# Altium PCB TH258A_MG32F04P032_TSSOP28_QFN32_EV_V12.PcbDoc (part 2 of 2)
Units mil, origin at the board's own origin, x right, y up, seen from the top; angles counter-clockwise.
Board outline 4094.49 x 2637.8 mil, 2 copper layers (Top Layer, Bottom Layer); 115 components, 96 nets, 518 pads, 260 vias.
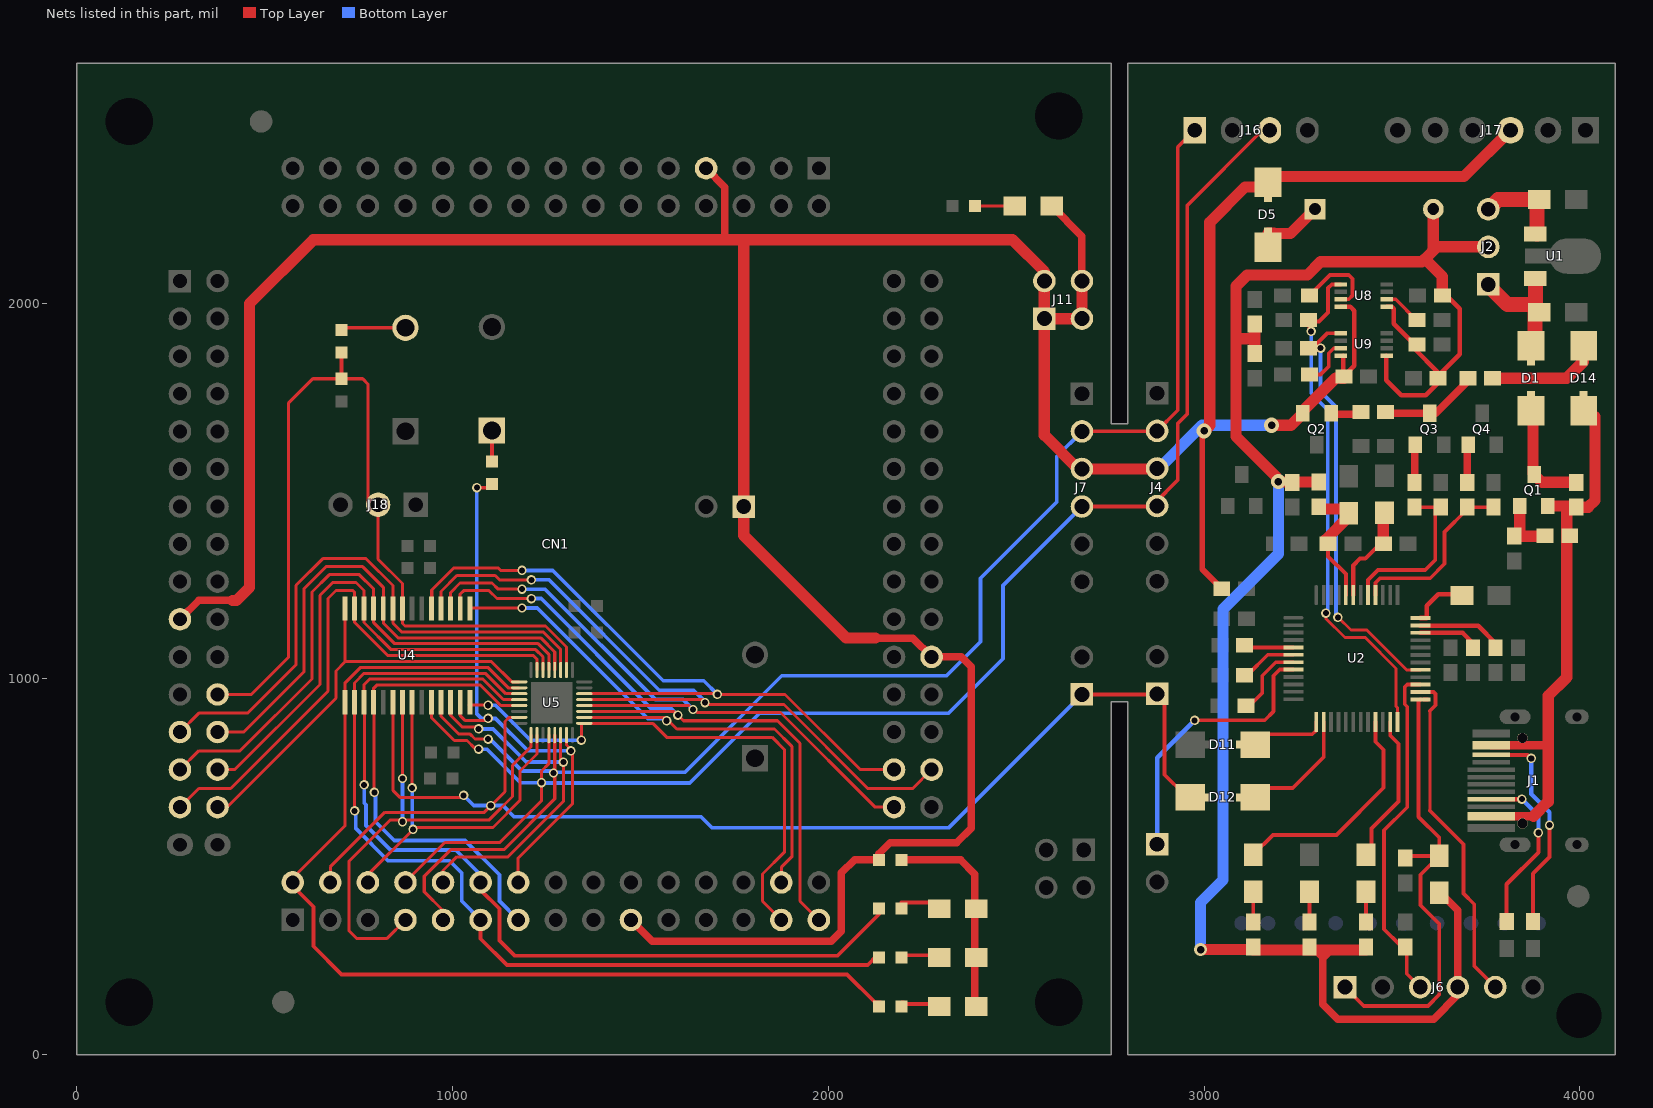
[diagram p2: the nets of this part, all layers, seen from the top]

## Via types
v1: diameter 20, hole 12, Top Layer to Bottom Layer, tented both sides, 172 vias
v2: diameter 25, hole 16, Top Layer to Bottom Layer, tented both sides, 58 vias
v3: diameter 30, hole 12, Top Layer to Bottom Layer, tented both sides, 14 vias
v4: diameter 25, hole 12, Top Layer to Bottom Layer, tented both sides, 6 vias
v5: diameter 40, hole 20, Top Layer to Bottom Layer, tented both sides, 3 vias
v6: diameter 28, hole 16, Top Layer to Bottom Layer, tented both sides, 3 vias
v7: diameter 30, hole 16, Top Layer to Bottom Layer, tented both sides, 2 vias
v8: diameter 15, hole 12, Top Layer to Bottom Layer, tented both sides, 1 vias
v9: diameter 35, hole 20, Top Layer to Bottom Layer, tented both sides, 1 vias

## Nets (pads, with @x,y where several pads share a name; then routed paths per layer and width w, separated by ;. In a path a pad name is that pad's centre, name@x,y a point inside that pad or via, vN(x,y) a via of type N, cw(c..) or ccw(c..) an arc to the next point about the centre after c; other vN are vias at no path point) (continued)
MLINK_TXD: CN1.4 D12.1 J5.1 J8.1 U4.6 U5.15 | length 3562.3
  Top Layer w8: CN1.4@675.04,458.74 675.04,500.04 820,645 1085,645 1102.5,662.5 1140.04,700.04 1140.04,886.47 1151.33,897.76 U5.15@1177.8,897.76 ; U4.6@842.24,937.5 842.24,702.76 860,685 v2@1020,685 ; J5.1@2875.04,960 J5.1@2880.81,954.23
  Top Layer w10: J8.1@2675.04,958.74 J5.1@2875.04,958.74 ; J5.1@2895.04,958 2895.04,745 D12.1@2948.43,691.61
  Bottom Layer w10: v2(1030,690) 1057,663 v2(1102,663) 1134.5,663 1164.5,633 1662,633 1691.26,603.74 2320.04,603.74 J8.1@2675.04,958.74
NetC2_2: C2.2 Q1.1 R5.2 | length 165
  Top Layer w30: R5.2@3825.04,1380 R5.2@3840.04,1380 ; Q1.1@3840.04,1460 R5.2@3840.04,1380 ; C2.2@3910.04,1380 3907,1380 R5.2@3840.04,1380
NetC6_1: C6.1 C7.2 R10.2 U2.44 | length 332.7
  Top Layer w11: C7.2@3330,1360 3330,1326 3377.23,1278.77 U2.44@3377.23,1223.13
  Top Layer w30: R10.2@3320.04,1452 3385,1452 C6.1@3385,1440.79 3385,1432 3324,1371 C7.2@3324,1366
NetC8_2: C8.2 C9.1 U2.43 | length 251
  Top Layer w11: U2.43@3396.92,1223.13 3396.92,1301.92 3415,1320 3429,1320 3465.5,1356.5 3477,1356.5 C8.2@3480.5,1356.5
  Top Layer w30: C8.2@3477,1360 C9.1@3477,1426.05
NetC11_1: C11.1 U2.36 | length 149.7
  Top Layer w12: U2.36@3575.5,1162.16 3592.2,1162.16 3592.2,1194.68 3622.9,1225.39 C11.1@3679.94,1225.39
NetD1_1: D1.1 Q1.3 R1.2 | length 276.4
  Top Layer w30: D1.1@3875,1698.39 3875,1546.98 Q1.3@3878.04,1543.94 3898.98,1523 R1.2@3990.04,1523
NetD2_1: D2.1 R6.2 | length 80.8
  Top Layer w10: R6.2@3130.59,353.26 D2.1@3130.59,434.05
NetD3_1: D3.1 R9.2 | length 80.8
  Top Layer w10: R9.2@3430.59,353.26 D3.1@3430.59,434.05
NetD4_1: D4.1 R11.2 | length 80.8
  Top Layer w10: R11.2@3280.59,353.26 D4.1@3280.59,434.05
NetD5_1: D5.1 SW1.1 | length 154.2
  Top Layer w30: D5.1@3170,2185.93 3185.93,2185.93 3185,2185 3230.04,2185 SW1.1@3295.04,2250
NetD8_1: D8.1 D9.1 D10.1 R58.1 | length 550.6
  Top Layer w20: R58.1@2195.04,518.74 2351.9,518.74 2390,480.64 2390,388.74 2390,258.74 D10.1@2390,140.79
NetD8_2: D8.2 R54.2 | length 95.8
  Top Layer w10: 2195.04,405 D8.2@2290.79,405
NetD9_2: D9.2 R55.2 | length 95.8
  Top Layer w10: R55.2@2189.94,265 2195.04,265 D9.2@2285.73,265
NetD10_2: D10.2 R56.2 | length 95.8
  Top Layer w10: R56.2@2196.58,140 R56.2@2200,140 ; R56.2@2199.94,135 D10.2@2292.3,135
NetD11_1: D11.1 U2.13 | length 188.6
  Top Layer w10: D11.1@3136.65,852.74 3288.04,852.74 3298.49,863.19 U2.13@3298.49,885.65
NetD12_2: D12.2 U2.14 | length 296
  Top Layer w10: D12.2@3150.04,709.74 3236.14,709.74 3318.18,791.78 U2.14@3318.18,885.65
NetD13_2: D13.2 R43.2 | length 105.8
  Top Layer w8: R43.2@2390.04,2258.74 D13.2@2495.83,2258.74
NetD14_2: D14.2 R17.1 | length 272.5
  Top Layer w30: R17.1@3768,1800 3965,1800 D14.2@4009.08,1844.07 ; D14.2@3998.15,1868.15 D14.2@4010,1868.15 ; D14.2@4004.08,1844.07 D14.2@4005,1845
NetJ1_A5: J1.A5 R26.1 | length 460.3
  Top Layer w11: J1.A5@3763.84,679.9 v2(3845.59,679.9) ; R26.1@3805.04,354.74 3805.04,453.74 3890.04,538.74 v2@3890.04,590.74
  Bottom Layer w11: v2(3845.59,679.9) 3889.59,635.9 v2(3889.59,590.74)
NetJ1_B5: J1.B5 R27.2 | length 582.9
  Top Layer w11: J1.B5@3763.84,798.01 3861.32,798.01 v2(3870.59,788.74) ; R27.2@3875.04,354.74 3875.04,481.74 3919.04,525.74 v2(3919.04,610.74)
  Bottom Layer w11: v2(3870.59,788.74) 3870.59,693.74 3919.04,645.29 v2(3919.04,610.74)
NetQ2_1: Q2.1 R18.2 | length 72
  Top Layer w20: Q2.1@3338,1703.94 R18.2@3410,1703.94
NetQ3_1: Q3.1 R19.2 | length 97.5
  Top Layer w20: R19.2@3560.04,1523 Q3.1@3560.04,1620.53
NetQ3_2: Q3.2 R17.2 R18.1 | length 242.2
  Top Layer w20: R18.1@3503.03,1706.97 Q3.2@3600.54,1706.97 3616.97,1706.97 3702,1792 R17.2@3702,1800
NetQ4_1: Q4.1 R23.2 | length 97.5
  Top Layer w20: R23.2@3700.04,1523 Q4.1@3700.04,1620.53
NetR15_1: R15.1 U2.35 | length 263.6
  Top Layer w12: U2.35@3575.5,1141.47 3605.04,1141.47 ; 3637.3,1141.47 3605.04,1141.47 ; R15.1@3775.59,1083 3775.59,1095 3729.12,1141.47 3605.04,1141.47
NetR16_1: R16.1 U2.34 | length 163.6
  Top Layer w12: U2.34@3575.5,1122.79 3687.8,1122.79 3715.59,1095 R16.1@3715.59,1083
NetR29_2: R29.2 U8.7 | length 202.9
  Top Layer w10: R29.2@3295,2035 3335,2075 3385,2075 3395,2065 3395,2020 3385.16,2010.16 U8.7@3363.98,2010.16 U8.7@3361.86,2010.16
NetR30_2: R30.2 U9.7 | length 132.5
  Top Layer w10: R30.2@3281,1810 3310,1810 3331.5,1831.5 3331.5,1866.5 3345.16,1880.16 U9.7@3363.98,1880.16
NetR59_1: R59.1 SW4.2 | length 165.6
  Top Layer w10: R59.1@709.45,1934.33 SW4.2@875.04,1934.33
NetR61_2: R61.2 SW3.1 | length 82.2
  Top Layer w10: R61.2@1105.04,1578.74 SW3.1@1105.04,1660.95
NetR64_2: R64.2 U8.2 | length 108.2
  Top Layer w10: U8.2@3486.02,2010.16 3509.84,2010.16 R64.2@3566,1954 ; R64.2@3553.5,1968.5 R64.2@3557,1965
P44: J6.5 U2.26 | length 900.8
  Top Layer w8: 3600.59,650 3600.59,915
  Top Layer w10: U2.26@3575.5,965.31 3610.28,965.31 3615.59,960 3615.59,930 3600.59,915 ; 3600.59,650 3690.59,560 3690.59,429 3719.14,400.45 3719.14,235.9 J6.5@3775.04,180
P45: J6.3 R25.1 U2.27 | length 931.6
  Top Layer w10: R25.1@3539.32,290.72 3539.32,287 3539.32,215.72 J6.3@3575.04,180 ; R25.1@3540.59,292 3535.59,292 3521.03,292 3479.04,333.99 3479.04,597.19 3540.59,658.74 3540.59,926 3534,932.59 3534,978.41 3540.58,984.99 U2.27@3575.5,984.99 ; J6.3@3576.32,181.28 J6.3@3583.59,174
PA0_BOOT0: CN1.114 J18.2 R59.2 R60.1 U4.22 U5.2 | length 2412.8
  Top Layer w8: CN1.114@375.04,958.74 465.04,958.74 563.47,1057.18 563.47,1733.53 628.68,1798.74 R60.1@705.04,1798.74 761.26,1798.74 775.04,1784.96 775.04,1463.74 J18.2@775.04,1458.74 ; J18.2@802.2,1463.74 802.2,1318.74 867.24,1253.7 U4.22@867.24,1187.5 867.24,1147.76 874,1141 1247.78,1141 1303.78,1085 U5.2@1303.78,1023.74
  Top Layer w10: R60.1@705.04,1798.74 R59.2@705.04,1868.74
PA1: CN1.115 U4.23 U5.3 | length 1541.2
  Top Layer w8: CN1.115@275.04,858.74 325.04,908.74 455.04,908.74 583.93,1037.63 583.93,1248.93 655,1320 770,1320 841.65,1248.35 U4.23@841.65,1187.5 841.65,1148.35 864.75,1125.25 1241.26,1125.25 1288.03,1078.48 U5.3@1288.03,1023.74
PA2: CN1.116 U4.24 U5.4 | length 1407
  Top Layer w8: CN1.116@375.04,858.74 445.04,858.74 605.15,1018.85 605.15,1240.15 663.79,1298.79 761.21,1298.79 816.06,1243.94 U4.24@816.06,1187.5 816.06,1148.94 855.5,1109.5 1234.73,1109.5 1272.28,1071.95 U5.4@1272.28,1023.74
PA3: CN1.117 U4.25 U5.5 | length 1518.2
  Top Layer w8: CN1.117@271.02,758.74 CN1.117@275.04,758.74 325.04,808.74 435.04,808.74 626.36,1000.06 626.36,1231.36 672.57,1277.57 752.43,1277.57 790.47,1239.53 U4.25@790.47,1187.5 790.47,1149.53 846.24,1093.76 1228.21,1093.76 1256.54,1065.43 U5.5@1256.54,1023.74
PA4: CN1.118 U4.26 U5.6 | length 1377.6
  Top Layer w8: CN1.118@375.04,758.74 421.02,758.74 647.57,985.3 647.57,1222.57 681.36,1256.36 743.64,1256.36 764.88,1235.12 U4.26@764.88,1187.5 764.88,1150.12 836.99,1078.01 1221.69,1078.01 1240.79,1058.91 U5.6@1240.79,1023.74
PA5: CN1.119 U4.27 U5.7 | length 1476.5
  Top Layer w8: CN1.119@275.04,658.74 325.04,708.74 410.04,708.74 668.79,967.49 668.79,1213.79 690.15,1235.15 734.85,1235.15 739.29,1230.71 U4.27@739.29,1187.5 ; U4.27@740,1180 740,1150 827.74,1062.26 1215.16,1062.26 1225.04,1052.38 U5.7@1225.04,1023.74
PA6: CN1.120 U4.28 U5.9 | length 1170.9
  Top Layer w8: CN1.120@375.04,658.74 400.04,658.74 690,948.7 690,1021.3 713.7,1045 ; U4.28@713.7,1187.5 713.7,1045 ; U5.9@1177.8,992.24 1157.76,992.24 1103.49,1046.51 715.21,1046.51 713.7,1045
PA7: CN1.2 R56.1 U4.1 U5.10 | length 2866
  Top Layer w8: CN1.2@575.04,468.74 CN1.2@575.04,458.74 575.04,470.04 714.29,609.29 U4.1@714.29,937.5 ; U4.1@713.7,937.5 713.7,988.7 755.76,1030.76 1094.24,1030.76 1148.5,976.5 U5.10@1177.8,976.5
  Top Layer w10: CN1.2@575.04,458.74 575.04,448.74 630.04,393.74 630.04,288.74 705.04,213.74 2050.04,213.74 2123.78,140 2135.04,140 R56.1@2140,140
PA11: CN1.6 U4.8 U5.18 | length 1046.7
  Top Layer w8: CN1.6@775.04,468.74 CN1.6@775.04,458.74 775.04,478.74 895.65,599.35 901.3,605 1108,605 1180.04,677.04 1180.04,755.04 1225.04,800.04 U5.18@1225.04,850.51 ; v2(892.83,710) U4.8@892.83,937.5
  Bottom Layer w10: v2@892.83,600 v2(892.83,710)
  other v2: 895,600
PA12: CN1.7 U4.7 U5.17 | length 1367.3
  Top Layer w8: v2(867.24,735) U4.7@867.24,937.5 ; CN1.7@875.04,358.74 825.04,308.74 746,308.74 725.04,329.7 725.04,515.04 835,625 1098,625 1160.04,687.04 1160.04,770.04 1209.29,819.29 U5.17@1209.29,850.51
  Bottom Layer w10: v2@867.24,625 v2(867.24,735)
  other v2: 867.24,620
PA13_SWDIO: CN1.8 J4.4 J7.4 J16.3 U4.10 U5.20 | length 4221.6
  Top Layer w8: CN1.8@875.04,458.74 CN1.8@875.04,460.04 ; CN1.8@875.04,478.74 CN1.8@875.04,460.04 ; U4.10@944.02,937.5 944.02,897.2 1005.22,836 1039,836 v2@1059.5,815.5 ; U5.20@1256.54,850.51 1256.54,774.54 1237,755 v2(1237,724) 1237,675.7 1126.04,564.74 979.74,564.74 CN1.8@875.04,460.04
  Top Layer w10: J7.4@2675.04,1458.74 J4.4@2860.04,1458.74 ; J4.4@2868.04,1467 2930.04,1529 2930.04,1680 2955.04,1705 2955.04,2260.04 3155,2460 J16.3@3175.04,2460
  Bottom Layer w10: v2(1070,813) 1092,813 1181,724 v2(1237,724) ; v2@1237,723 1631.73,723 1817.47,908.74 2320.04,908.74 2465.04,1053.74 2465.04,1248.74 J7.4@2675.04,1458.74
PA14_SWCLK: CN1.9 J4.2 J7.2 J16.1 U4.11 U5.21 | length 4127.5
  Top Layer w8: U4.11@969.61,937.5 969.61,900.39 1016,854 1046,854 1060,840 v2(1095,840) ; CN1.9@975.04,358.74 975.04,383.74 925.04,433.74 925.04,475.04 995.74,545.74 1137.04,545.74 1272.28,680.98 1272.28,749.74 U5.21@1272.28,850.51
  Top Layer w10: J7.2@2675.04,1658.74 J4.2@2875.04,1658.74 ; J4.2@2875.04,1660 2930.04,1715 2930.04,2415 J16.1@2975.04,2460
  Bottom Layer w10: v2(1095,840) 1100,840 1185,755 v2@1262.05,755 ; v2@1264.04,753.74 1265.12,753.74 1266.86,752 1269.04,752 1619.72,752 1876.46,1008.74 2315.04,1008.74 2405.04,1098.74 2405.04,1267.74 2608.04,1470.74 2608.04,1591.74 J7.2@2675.04,1658.74
  other v2: 1269.04,749.74
PA15: CN1.10 U4.12 U5.22 | length 991.4
  Top Layer w8: CN1.10@975.04,458.74 975.04,490.04 1011.74,526.74 1148.04,526.74 1295.67,674.38 1295.67,778.1 v2(1295.04,778.74) 1288.03,785.75 U5.22@1288.03,850.51 ; U4.12@995.2,937.5 995.2,902.8 1026,872 v2@1070,872
  Bottom Layer w10: v2(1070,867) 1108,867 1196.26,778.74 v2(1295.04,778.74)
PASS: D3.2 U2.23 | length 394.2
  Top Layer w10: D3.2@3445.59,530 3445.59,532.47 3445.59,602.29 3517.04,673.74 3517.04,827.74 3495.34,849.44 U2.23@3495.34,885.65
PB0: CN1.11 R55.1 U4.2 U5.11 | length 2484.5
  Top Layer w8: U4.2@739.29,937.5 739.29,989.29 765.02,1015.02 1087.71,1015.02 1141.98,960.75 U5.11@1177.8,960.75 ; v2@739.88,642.74 v2(739.88,649) U4.2@739.88,937.5
  Top Layer w10: CN1.11@1075.04,358.74 1075.04,308.74 1145.04,238.74 2105.04,238.74 R55.1@2130.04,263.74
  Bottom Layer w10: v2@739.88,642.74 v2@743.05,639.57 ; v2@743.05,642.74 v2@743.05,639.57 ; CN1.11@1075.04,358.74 1025.04,408.74 1025.04,483.74 992.48,516.3 828.7,516.3 743.05,601.95 v2@743.05,639.57
PB1: CN1.12 R54.1 U4.3 U5.12 | length 2463
  Top Layer w8: U4.3@764.88,937.5 764.88,984.88 779.27,999.27 1081.19,999.27 1135.46,945 U5.12@1177.8,945 ; v2@765.47,718 U4.3@765.47,937.5
  Top Layer w10: CN1.12@1075.04,458.74 1075.04,438.74 1125.04,388.74 1125.04,303.74 1165.04,263.74 2025.04,263.74 2135.04,373.74 R54.1@2135.04,388.74
  Bottom Layer w10: v2@765.51,720.64 765.51,718 765.51,669.49 770,665 770,610 835,545 1008.78,545 1075.04,478.74 CN1.12@1075.04,458.74
  other v2: 765,718
PB2: CN1.13 U4.4 U5.13 | length 1299.1
  Top Layer w8: U4.4@790.47,937.5 790.47,975.47 798.52,983.52 1074.67,983.52 1128.93,929.25 U5.13@1177.8,929.25 ; v2@791.06,698 U4.4@791.06,937.5
  Bottom Layer w10: v2(792.04,698) 795.2,694.83 795.2,619.8 845,570 1033.78,570 1125.04,478.74 1125.04,408.74 CN1.13@1175.04,358.74
PB3: CN1.14 R61.1 U4.13 U5.23 | length 1513.4
  Top Layer w8: U4.13@1020.04,928.74 U4.13@1020.79,928.74 ; U4.13@1020.79,937.5 U4.13@1020.79,928.74 ; v2(1095,895) 1090,890 1033,890 1020.79,902.21 U4.13@1020.79,928.74 ; CN1.14@1175.04,458.74 1175.04,523.74 1320.04,668.74 1320.04,807.74 1317.04,810.74 1303.78,824 U5.23@1303.78,850.51 ; CN1.14@1190.04,458.74 CN1.14@1190.04,463.74
  Top Layer w10: v2(1065.04,1508.74) R61.1@1105.04,1508.74
  Bottom Layer w10: v2(1065.04,1508.74) v2(1065.04,1508.74) 1065,907 1077,895 v2(1095,895) 1115,895 1201.26,808.74 v2(1315.04,808.74)
PB4: CN1.27 U4.14 U5.25 | length 1441.8
  Top Layer w8: U4.14@1044,930 1046.38,930 v2(1095,930) ; v2(1343,837) U5.25@1343,882.01 ; U5.25@1351.02,882.01 1532.77,882.01 1570.04,844.74 1850.76,844.74 1883.04,812.46 1883.04,538.75 1825.04,480.75 1825.04,408.74 CN1.27@1875.04,358.74
  Bottom Layer w10: v2(1095,930) 1115,930 1208,837 v2(1343,837)
PB5: CN1.28 U4.15 U5.26 | length 1625.4
  Top Layer w8: U4.15@1046.38,1188.74 v2(1185.04,1188.74) ; U5.26@1351.02,897.76 1566.02,897.76 1572.54,891.24 1597.04,866.74 1857.04,866.74 1903.04,820.74 1903.04,526.74 1875.04,498.74 CN1.28@1875.04,458.74 CN1.28@1875.04,478.74
  Bottom Layer w10: v2(1185.04,1188.74) 1225.78,1188.74 1519.52,895 1563.78,895 v2(1570.04,888.74)
PB6: CN1.29 U4.16 U5.27 | length 1858.4
  Top Layer w8: U4.16@1020.79,1187.5 1020.79,1225.79 1030,1235 1097.21,1235 1118.47,1213.74 v2(1210.04,1213.74) ; U5.27@1351.02,913.5 1590.04,913.5 1599.92,903.62 1614.8,888.74 1865.04,888.74 1925.04,828.74 1925.04,408.74 CN1.29@1975.04,358.74
  Bottom Layer w10: v2(1210.04,1213.74) 1236.13,1213.74 1529.87,920 1583.78,920 v2(1600.04,903.74)
PB7: CN1.32 U4.17 U5.28 | length 1772.3
  Top Layer w8: U4.17@995.2,1187.5 995.2,1230.2 1020,1255 1105.5,1255 1121.76,1238.74 v2(1185.04,1238.74) ; U5.28@1351.02,929.25 1629.53,929.25 v2(1640.04,918.74) ; v2@1641.54,920.24 1651.03,910.74 1873.04,910.74 2125.04,658.74 CN1.32@2175.04,658.74
  Bottom Layer w10: v2(1185.04,1238.74) 1246.49,1238.74 1540.23,945 1613.78,945 v2(1640.04,918.74)
PB8: CN1.33 U4.18 U5.29 | length 1950.9
  Top Layer w8: U4.18@969.61,1187.5 969.61,1232.89 1011.72,1275 1113.78,1275 1125.04,1263.74 v2(1210.04,1263.74) ; U5.29@1351.02,945 1668.78,945 1674.54,939.24 v2@1682.05,931.73 ; v2@1680.04,931.73 v2@1682.05,931.73 ; CN1.33@2275.04,758.74 2225.04,708.74 2105.04,708.74 1882.05,931.73 v2@1682.05,931.73
  Bottom Layer w10: v2(1210.04,1263.74) 1256.84,1263.74 1550.58,970 1641.77,970 v2@1673.54,938.24
  other v2: 1672.04,936.74
PB9: CN1.34 U4.19 U5.30 | length 1898.3
  Top Layer w8: U4.19@945,1180 945,1187.5 945,1236.57 1003.43,1295 1122.06,1295 1128.32,1288.74 v2(1185.04,1288.74) ; U5.30@1351.02,960.75 v2@1698.03,960.75 ; v2@1702.54,956.24 v2@1700.04,958.74 ; v2@1705.04,960.75 v2@1698.03,960.75 ; CN1.34@2175.04,758.74 2085.04,758.74 1885.04,958.74 v2(1705.04,958.74) v2@1700.04,958.74 ; v2@1698.03,960.75 v2@1700.04,958.74
  Bottom Layer w10: v2(1185.04,1288.74) 1267.2,1288.74 1560.94,995 1668.78,995 v2(1705.04,958.74)
RST: C12.2 J6.1 R22.2 U2.25 | length 1228.1
  Top Layer w10: J6.1@3375.04,180 3425.04,130 3595.59,130 3625.59,160 3625.59,348 3575.59,398 3575.59,479.21 C12.2@3625.59,529.21 ; R22.2@3541.8,529.21 C12.2@3625.59,529.21 ; U2.25@3575.59,945 3570.59,940 3570.59,633 3625.59,578 C12.2@3625.59,529.21 ; U2.25@3585.04,945.62 U2.25@3594.42,945.62
RST_CTRL_51: R19.1 R20.1 U2.41 | length 451.6
  Top Layer w10: U2.41@3436.29,1223.13 3436.29,1263.29 3463,1290 3588.74,1290 3615.04,1316.3 R20.1@3615.04,1457 ; R19.1@3560.04,1457 R20.1@3615.04,1457 ; R20.1@3630.04,1457 R20.1@3615.04,1457
RST_CTRL_ARM: R23.1 R24.1 U2.40 | length 474.1
  Top Layer w10: U2.40@3455.97,1223.13 3455.97,1256.14 3467.84,1268 3601.74,1268 3640.04,1306.3 3640.04,1391.3 R23.1@3697.5,1448.76 ; R23.1@3700.04,1457 R24.1@3770.04,1457
SWD_SCL_DIR: R63.2 U2.29 U9.5 | length 1149.4
  Top Layer w8: v2@3356.5,1164.5 3391,1130 3433,1130 3538.64,1024.36 U2.29@3575.5,1024.36
  Top Layer w10: R63.2@3289,1869 R63.2@3295,1875 ; R63.2@3290,1883 R63.2@3290.22,1882.64 ; R63.2@3292.47,1879.04 R63.2@3290.22,1882.64 ; R63.2@3292.93,1875 R63.2@3295,1875 ; v2@3311.93,1875 3310,1875 R63.2@3295,1875 ; U9.5@3363.98,1919.53 3327.11,1919.53 3298.79,1891.21 R63.2@3290.22,1882.64
  Bottom Layer w10: v2(3310,1880) 3310,1764.49 3351,1723.49 3351,1495 ; 3351,1505 3351,1495 ; v2@3361,1160 3356.5,1164.5 3351,1170 3351,1495
  other v2: 3356,1164
SWD_SDA_DIR: R62.2 U2.24 U8.5 | length 1381.2
  Top Layer w8: v2(3324,1175) 3324,1161 3375,1110 3429,1110 3511,1028 3511,927 3515.03,922.97 U2.24@3515.03,885.65
  Top Layer w10: v2@3280,1925 R62.2@3280,1951 ; R62.2@3282,1951 R62.2@3285,1951 ; R62.2@3285,1957 3285,1955 R62.2@3285,1951 ; U8.5@3363.98,2049.53 3339.53,2049.53 3330,2040 3330,1975 3306,1951 R62.2@3285,1951
  Bottom Layer w10: v2(3285,1925) 3285,1760 3329,1716 3329,1485 ; v2@3329,1175 3329,1485 ; 3329,1505 3329,1485
TOOL_OPTION0: R2.1 U2.5 | length 121.1
  Top Layer w10: R2.1@3118.04,1080 3121.96,1083.92 U2.5@3237.52,1083.92
TOOL_OPTION1: R3.1 U2.6 | length 142.8
  Top Layer w10: R3.1@3116.54,1011.54 3169.23,1064.23 U2.6@3237.52,1064.23
TOOL_OPTION2: R28.1 U2.7 | length 191.4
  Top Layer w10: R28.1@3121.04,928.74 3155.04,962.74 3155.04,1008.74 3190.85,1044.55 U2.7@3237.52,1044.55
USBOK: D2.2 U2.21 | length 605
  Top Layer w10: D2.2@3130.59,532.47 3183.12,585 3352.3,585 3477.67,710.37 3477.67,811.43 3455.97,833.13 U2.21@3455.97,885.65
VCC_USB: C2.1 D14.1 J1.A4 J1.A9 J1.M5 J1.M6 Q1.2 R1.1 | length 1456.2
  Top Layer w22: J1.A4@3763.84,634.61 3847.24,634.61 3876.67,634.61 ; J1.A9@3763.84,823.62 3847.24,823.62 3915.59,823.62
  Top Layer w30: 3876.67,634.61 3915.59,673.54 3915.59,823.62 3915.59,955 3964.92,1004.33 3964.92,1381.26 3964.92,1446.88 ; Q1.2@3915.04,1460 3967.04,1460 ; R1.1@3980.04,1457 R1.1@3990.04,1457 4022,1457 4040,1475 D14.1@4040,1698.39
VCP_OPTION: J3.1 U2.8 | length 845.4
  Top Layer w10: v2(2975,890) 3000.04,890 ; 3100.04,890 3000.04,890 ; U2.8@3237.52,1024.86 3201.16,1024.86 3185.04,1008.74 3185.04,913.74 3161.3,890 3000.04,890
  Bottom Layer w12: J3.1@2875.04,560 2875.04,790.04 v2(2975,890)
VDD: C12.1 J2.2 J6.4 R4.1 R6.1 R9.1 R10.1 R11.1 R12.1 R13.1 R14.2 R40.2 R41.2 SW1.2 U8.1 U9.1 | length 5168.8
  Top Layer w12: R11.1@3289.78,279.52 3290.3,279 3315.59,253.71 3315.94,253.36 ; 3315.95,251.65 3342.11,277.81 ; U9.1@3485,1860.47 3485,1795 3525,1755 3590,1755 3623,1788 R40.2@3623,1800 ; U8.1@3486.02,1990.47 3499.53,1990.47 3505,1985 3505,1945 ; 3505,1955 3505,1945 ; R40.2@3623,1798 R40.2@3623,1800 ; R40.2@3623,1805 R40.2@3623,1800 ; R40.2@3623,1815 3557.5,1880.5 3557,1881 3557,1890 3557,1893 3505,1945 ; R4.1@3640,2025 3680,1985 3680,1863.83 3623,1806.83 R40.2@3623,1800
  Top Layer w20: 3315.59,279 3315.59,253.71 3315.59,135 3355.59,95 3610.59,95 3675.04,159.45 J6.4@3675.04,180 3675.04,384.55 3635.59,424 C12.1@3635.59,430.79
  Top Layer w30: v9(2990.59,280) R6.1@3130.59,280 ; 3085,1645 3192.99,1537.01 v5@3192.99,1525 ; 3085,1645.64 3085,1905 ; R6.1@3130.59,279 3280.59,279 3290.3,279 3315.59,279 R9.1@3430.59,279 ; R12.1@3135,1866 3135,1905 ; R13.1@3135,1944 3135,1905 ; v5@3207.25,1524.26 3235,1524.26 R10.1@3305,1524.26 ; 3610,2150 SW1.2@3610,2250 ; R4.1@3634,2020 3634,2071 3587.5,2117.5 ; J2.2@3756.42,2150 3620,2150 3587.5,2117.5 ; 3085,1905 3085,2045 3115,2075 3275,2075 3310,2110 3580,2110 3587.5,2117.5 ; 3085,1905 3135,1905
  Bottom Layer w30: v9(2990.59,280) 2990.59,405 3050.59,465 3050.59,1185.55 3197.99,1332.95 v5(3197.99,1525)
VDD3: C5.1 J2.3 U1.1 | length 238.5
  Top Layer w40: J2.3@3756.42,2249.69 3782.68,2275.94 C5.1@3886.38,2275.94 ; U1.1@3886.38,2184.06 C5.1@3886.38,2275.94 ; C5.1@3892.17,2275.94 C5.1@3886.38,2275.94
VDD5: C4.1 D1.2 J2.1 U1.3 | length 287.7
  Top Layer w40: J2.1@3754.94,2048.21 3807.2,1995.94 3881.38,1995.94 U1.3@3881.38,2065.94 ; D1.2@3880,1901.61 C4.1@3880,1971.26
VDUT: C17.1 CN1.19 CN1.39 CN1.67 CN1.109 D5.2 D13.1 J4.3 J7.3 J11.1 J11.2 J11.3 J11.4 J17.3 JP3.1 Q2.2 R7.1 R58.2 U8.8 U9.8 | length 10517.8
  Top Layer w12: U8.8@3363.98,1990.47 3389.53,1990.47 3400,1980 3400,1833 C17.1@3372,1805 ; U9.8@3370,1860.47 3370,1805 C17.1@3371,1804
  Top Layer w15: v5@2995,1660.64 2995,1660 2995,1292 R7.1@3047,1240
  Top Layer w20: CN1.109@275.04,1158.74 325.04,1208.74 415.04,1208.74 ; CN1.19@1475.04,358.74 1532.14,301.64 2007.94,301.64 2035.04,328.74 2035.04,483.74 2070.04,518.74 R58.2@2135.04,518.74 2135.04,534.74 2165.04,564.74 2342.14,564.74 2379.94,602.54 2379.94,1032.74 2353.94,1058.74 CN1.39@2275.04,1058.74 2225.04,1108.74 2125.04,1108.74 ; CN1.67@1675.04,2358.74 1725.04,2308.74 1725.04,2168.74 ; D13.1@2594.25,2258.74 2675.04,2177.95 J11.4@2675.04,2058.74
  Top Layer w30: 415.04,1208.74 425.04,1208.74 460.04,1243.74 460.04,1998.74 630.04,2168.74 1725.04,2168.74 1775.04,2168.74 ; 2125.04,1108.74 2048.04,1108.74 1775.04,1381.74 JP3.1@1775.04,1458.74 1775.04,2168.74 ; J7.3@2675.04,1548.74 2670.04,1553.74 J7.3@2665.04,1558.74 ; J11.4@2675.04,2058.74 J11.3@2675.04,1958.74 J11.1@2575.04,1958.74 ; J4.3@2875.04,1558.74 J7.3@2675.04,1558.74 J7.3@2665.04,1558.74 ; v5@2999.97,1660.03 3015,1675.06 3015,2215 3109.06,2309.06 3169.09,2309.06 3175.83,2315.79 3196.65,2336.61 3691.65,2336.61 J17.3@3815.04,2460 ; v5(3180,1675) 3231.03,1675 Q2.2@3263,1706.97 ; Q2.2@3259.98,1709.98 C17.1@3350,1800 ; C17.1@3365,1800 C17.1@3372,1800 ; 1775.04,2168.74 2490.04,2168.74 2575.04,2083.74 J11.2@2575.04,2058.74 J11.1@2575.04,1958.74 ; J11.1@2575.04,1958.74 2575.04,1648.74 J7.3@2665.04,1558.74
  Bottom Layer w30: J4.3@2876.89,1556.89 2877.52,1557.52 2990,1670 2995,1675 3000,1675 v5(3180,1675)
  other v5: 3000,1660
pads on no net: CN1.1 CN1.15 CN1.16 CN1.18 CN1.20 CN1.21 CN1.22 CN1.23 CN1.24 CN1.25 CN1.26 CN1.30 CN1.31 CN1.35 CN1.36 CN1.37 CN1.38 CN1.40 CN1.42 CN1.43 CN1.44 CN1.45 CN1.46 CN1.47 CN1.48 CN1.49 CN1.50 CN1.51 CN1.52 CN1.53 CN1.54 CN1.55 CN1.56 CN1.57 CN1.58 CN1.59 CN1.60 CN1.61 CN1.62 CN1.63 CN1.64 CN1.65 CN1.66 CN1.68 CN1.70 CN1.71 CN1.72 CN1.73 CN1.74 CN1.75 CN1.76 CN1.77 CN1.78 CN1.79 CN1.80 CN1.81 CN1.82 CN1.83 CN1.84 CN1.85 CN1.86 CN1.87 CN1.88 CN1.89 CN1.90 CN1.91 CN1.92 CN1.93 CN1.94 CN1.95 CN1.96 CN1.97 CN1.98 CN1.99 CN1.100 CN1.101 CN1.102 CN1.103 CN1.104 CN1.105 CN1.106 CN1.108 CN1.110 CN1.111 CN1.112 CN1.113 CN1.121 CN1.122 J1.A8 J1.B8 J6.6 J7.1 U2.1 U2.2 U2.3 U2.4 U2.28 U2.30 U2.32 U2.37 U2.38 U2.39 U2.46 U5.8 U5.16 U5.24 U5.32 U5.33 U8.3 U8.6 U9.3 U9.6

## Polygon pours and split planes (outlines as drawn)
GND_POWER on Bottom Layer "Top Layer-No Net" (hatched 90Degree grid 10 track 10, remove dead copper, pour order 1001): 25,20 4070,20 4070,2610 25,2610
GND_POWER on Top Layer "Top Layer-No Net" (hatched 90Degree grid 10 track 10, remove dead copper, pour order 1001): 25,20 4070,20 4070,2610 25,2610

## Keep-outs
Top Layer:
  circle w5: c3995.59,421.9 r59.06
  circle w5: c550,140 r59.06
  circle w5: c491,2483.43 r59.06
Keep-Out Layer:
  circle w7.88: c140,140 r133.86
  circle w7.88: c2613.39,140 r133.86
  circle w7.88: c2613.39,2497.8 r133.86
  circle w7.88: c140,2483.43 r133.86
  lines w15: 2796.69,938.74 2753.39,938.74 2753.39,0 0,0 0,2637.8 2753.39,2637.8 2753.39,1678.74 2796.69,1678.74 ; 4094.49,1.26 4094.49,2639.06 4094.49,1.26

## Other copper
Top Layer:
  pour cut-out: 2710,2623.74 2830,2623.74 2830,0 2710,0
Bottom Layer:
  pour cut-out: 2710,2625 2830,2625 2830,0 2710,0

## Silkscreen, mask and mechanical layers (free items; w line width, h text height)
Top Overlay:
  circle w10: c140,140 r137.8
  circle w4: c2613.39,140 r137.8
  circle w10: c2613.39,2497.8 r137.8
  circle w10: c140,2483.43 r137.8
  region: 3004.44,1068.04 2957.54,1093.69 2959.44,1078.04 2930.04,1078.04 2930.04,1058.04 2959.44,1058.04 2957.54,1043.69
  region: 2930.99,955.86 2977.89,930.21 2975.99,945.86 3005.04,945.86 3005.04,965.86 2975.99,965.86 2977.89,980.21
  region: 2877.11,264.05 2902.77,335.95 2887.11,334.05 2887.11,394.05 2867.11,394.05 2867.11,334.05 2852.77,335.95
  region: 2614.4,1059.29 2567.5,1084.94 2569.4,1069.29 2519.4,1069.29 2519.4,1049.29 2569.4,1049.29 2567.5,1034.94
  region: 2520.95,947.11 2567.86,921.46 2565.95,937.11 2615.95,937.11 2615.95,957.11 2565.95,957.11 2567.86,971.46
  text "When J16 Open" at 2820,2580 h45
  text "SW1 must be off" at 2820,2520.64 h45
  text "GND" at 1595.04,2423.74 h50 r90
  text "VDUT" at 1695.04,2423.74 h50 r90
  text "RST" at 3419.94,2415 h37 r90
  text "GND" at 3469.94,2415 h37 r90
  text "Power" at 3385,2350 h45
  text "Off" at 3250.9,2348.32 h45
  text "On" at 3605,2345 h45
  text "SCL" at 3930,2325 h35 r90
  text "CLK" at 4035,2325 h35 r90
  text "SDA" at 3739.94,2320 h37 r90
  text "VCC" at 3830,2320 h37 r90
  text "VDD3" at 3695,2195 h37 r90
  text "Power" at 2450.04,2158.74 h50
  text "VDD" at 3605,2115 h37
  text "VDD5" at 3575,2060 h37
  text "Key1" at 795.04,2048.74 h50
  text "Key2" at 1035.04,2048.74 h50
  text "2024.11" at 1822.04,1932.74 h35
  text "TH258A_MG32F04P032" at 1243.04,1851.74 h50
  text "VDUT" at 2515.04,1840.64 h50
  text "_TSSOP28_QFN32_EV_V12" at 1200.04,1759.74 h45
  text "SCL" at 2530.04,1643.74 h33
  text "VDUT" at 2495.04,1538.74 h33
  text "SDA" at 2525.04,1443.74 h33
  text "GND" at 2525.04,1338.74 h33
  text "RST" at 2530.04,1238.74 h33
  text "GND" at 85.04,1228.74 h50
  text "RESET" at 1715.04,1173.74 h50
  text "GND" at 2340.04,1138.74 h50
  text "PA8_TX" at 2490,1135 h38
  text "VDUT" at 45,1130.64 h50
  text "VDUT" at 2340.04,1033.74 h50
  text "PA0" at 439.94,933.74 h50
  text "PA9_RX" at 2500,850 h38
  text "PA2" at 440.04,830.64 h50
  text "PA1" at 95.04,828.74 h50
  text "PB9" at 1985.04,733.74 h50
  text "PB8" at 2340.04,733.74 h50
  text "PA4" at 440.04,730.64 h50
  text "PA3" at 75.04,728.74 h50
  text "PB7" at 1985.04,633.74 h50
  text "PA6" at 440.04,630.64 h50
  text "PA5" at 75.04,628.74 h50
  text "PA7" at 485,530 h50
  text "PA9" at 695.04,523.74 h50 r90
  text "PA11" at 795.04,523.74 h50 r90
  text "PA13" at 870.04,523.74 h50 r90
  text "PA15" at 995.04,523.74 h50 r90
  text "PB1" at 1095.3,524 h50 r90
  text "PB3" at 1200.04,523.74 h50 r90
  text "PB5" at 1900.04,523.74 h50 r90
  text "GND" at 2545,320 h50
  text "J3" at 2835.04,201.9 h45
  text "PB0" at 1100.04,168.74 h50 r90
  text "PB2" at 1200.04,168.74 h50 r90
  text "GND" at 1405.04,168.74 h50 r90
  text "PB4" at 1900.04,168.74 h50 r90
  text "PB6" at 2000.04,168.74 h50 r90
  text "PA8" at 695.04,163.74 h50 r90
  text "Open Disable VCP." at 2815.59,130 h40
  text "Open Disable VCP." at 2815.59,130 h40
  text "VDUT" at 1500.04,124.45 h50 r90
  text "PA10" at 795.04,123.74 h50 r90
  text "PA12" at 900,120 h50 r90
  text "PA14" at 1005,120 h50 r90
  text "Short Enable VCP." at 2815.59,35 h40
  text "Short Enable VCP." at 2815.59,35 h40
Mechanical 1:
  circle w7.88: c2775.04,1613.74 r27
  circle w7.88: c2775.04,1503.74 r27
  circle w7.88: c2775.04,1416.74 r25
  circle w7.88: c2775.04,1298.74 r25
  circle w7.88: c2775.04,1008.74 r33
  lines w7.88: 2753.39,1078.74 2753.39,1232.74 2796.69,1232.74 2796.69,1078.74 2753.39,1078.74
  lines w8.88: 4094.49,0 4094.49,2637.8 ; 4094.49,0 4094.49,2637.8 ; 4094.49,0 2796.69,0 2796.69,938.74 2753.39,938.74 2753.39,0 0,0 0,2637.8 2753.39,2637.8 2753.39,1678.74 2796.69,1678.74 2796.69,2637.8 4094.49,2637.8
Mechanical 2:
  lines w6: 2775.04,1031.74 2775.04,1008.74 2798.04,1008.74 ; 2775.04,1321.74 2775.04,1298.74 2798.04,1298.74 ; 2775.04,1441.74 2775.04,1418.74 2798.04,1418.74 ; 2775.04,1526.74 2775.04,1503.74 2798.04,1503.74 ; 2775.04,1636.74 2775.04,1613.74 2798.04,1613.74

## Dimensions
0,0 to 0,2637.8 on Top Overlay
0,0 to 4094.49,0 on Top Overlay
